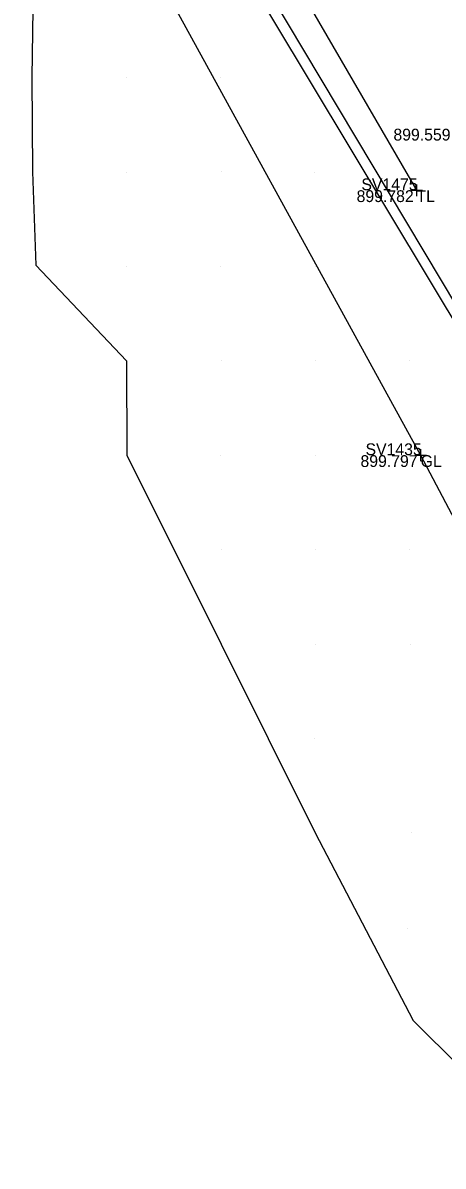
# Model space of a CAD drawing. Extents: x 1918148 to 1919797, y 624701 to 627089.
# Drawn here: x 1918830.7 to 1918866.3, y 625511 to 625607.8 of the extents above; entities that cross this region are included whole.
import ezdxf

# ---------------------------------------------------------------- set-up
doc = ezdxf.new("R2010")
doc.units = 0
for name, color, linetype in [('DT_X_Terrain_Boundary', 7, 'Continuous'), ('Ground Shots', 7, 'Continuous'), ('RD_X_Fence', 7, 'Continuous'), ('SV_X_Shot_Marker', 7, 'Continuous'), ('SV_X_Text_Comment', 7, 'Continuous'), ('SV_X_Text_Elevation', 7, 'Continuous'), ('SV_X_Text_Name', 7, 'Continuous'), ('UT_X_Gas', 7, 'Continuous'), ('UT_X_Overhead_Combined', 7, 'Continuous'), ('UT_X_Telecom', 7, 'Continuous')]:
    doc.layers.add(name, color=color, linetype=linetype)

msp = doc.modelspace()

# ---------------------------------------------------------------- linework, layer by layer
at = {"layer": 'DT_X_Terrain_Boundary'}
msp.add_lwpolyline([(1918796.762, 625701.528), (1918837.417, 625633.441), (1918839.502, 625611.203), (1918831.565, 625610.956), (1918831.449, 625603.209), (1918831.49, 625595.21), (1918831.786, 625587.295), (1918839.47, 625579.205), (1918839.493, 625571.214), (1918847.481, 625555.19), (1918855.45, 625539.209), (1918863.741, 625523.315), (1918871.72, 625515.381), (1918879.451, 625499.232)], dxfattribs=at)
at = {"layer": 'Ground Shots'}
for p, q in [((1918831.449, 625603.209), (1918831.449, 625603.209)), ((1918839.444, 625603.191), (1918839.444, 625603.191)), ((1918847.457, 625603.198), (1918847.457, 625603.198)), ((1918831.49, 625595.21), (1918831.49, 625595.21)), ((1918839.481, 625595.196), (1918839.481, 625595.196)), ((1918847.504, 625595.203), (1918847.504, 625595.203)), ((1918855.398, 625595.153), (1918855.398, 625595.153)), ((1918831.786, 625587.295), (1918831.786, 625587.295)), ((1918839.441, 625587.187), (1918839.441, 625587.187)), ((1918847.455, 625587.205), (1918847.455, 625587.205)), ((1918855.471, 625587.23), (1918855.471, 625587.23)), ((1918839.47, 625579.205), (1918839.47, 625579.205)), ((1918847.476, 625579.197), (1918847.476, 625579.197)), ((1918855.489, 625579.212), (1918855.489, 625579.212)), ((1918863.456, 625579.203), (1918863.456, 625579.203)), ((1918839.493, 625571.214), (1918839.493, 625571.214)), ((1918847.459, 625571.176), (1918847.459, 625571.176)), ((1918855.445, 625571.172), (1918855.445, 625571.172)), ((1918863.482, 625571.147), (1918863.482, 625571.147)), ((1918847.487, 625563.193), (1918847.487, 625563.193)), ((1918855.48, 625563.206), (1918855.48, 625563.206)), ((1918863.466, 625563.204), (1918863.466, 625563.204)), ((1918847.481, 625555.19), (1918847.481, 625555.19)), ((1918855.469, 625555.204), (1918855.469, 625555.204)), ((1918863.488, 625555.203), (1918863.488, 625555.203)), ((1918855.353, 625547.174), (1918855.353, 625547.174)), ((1918855.45, 625539.209), (1918855.45, 625539.209)), ((1918863.635, 625539.207), (1918863.635, 625539.207)), ((1918863.259, 625531.112), (1918863.259, 625531.112)), ((1918863.741, 625523.315), (1918863.741, 625523.315))]:
    msp.add_line(p, q, dxfattribs=at)
at = {"layer": 'RD_X_Fence'}
msp.add_lwpolyline([(1918745.788, 625786.434), (1918772.784, 625741.746), (1918796.762, 625701.528), (1918837.417, 625633.441), (1918845.82, 625619.995), (1919000.613, 625360.91)], dxfattribs=at)
at = {"layer": 'SV_X_Shot_Marker'}
for p, q in [((1918863.519, 625593.652), (1918864.519, 625593.652)), ((1918864.019, 625594.152), (1918864.019, 625593.152)), ((1918864.019, 625593.652), (1918864.019, 625593.652)), ((1918864.37, 625571.708), (1918864.37, 625570.708)), ((1918863.87, 625571.208), (1918864.87, 625571.208)), ((1918864.37, 625571.208), (1918864.37, 625571.208))]:
    msp.add_line(p, q, dxfattribs=at)
at = {"layer": 'UT_X_Gas'}
msp.add_lwpolyline([(1918759.168, 625917.084), (1918754.306, 625900.243), (1918749.452, 625846.761), (1918748.461, 625829.004), (1918743.942, 625797.46), (1918743.006, 625773.569), (1918765.829, 625740.859), (1918795.68, 625692.777), (1918822.428, 625647.505), (1918838.928, 625617.602), (1918864.37, 625571.208), (1918888.363, 625525.758), (1918914.136, 625478.379), (1918935.187, 625439.317), (1918956.473, 625399.657), (1918975.299, 625371.47), (1919011.933, 625334.484), (1919018.035, 625313.569)], dxfattribs=at)
at = {"layer": 'UT_X_Overhead_Combined'}
msp.add_lwpolyline([(1918749.028, 625800.122), (1918759.416, 625761.901), (1918898.018, 625531.272), (1919016.404, 625331.435)], dxfattribs=at)
at = {"layer": 'UT_X_Telecom'}
msp.add_lwpolyline([(1918746.049, 625787.637), (1918759.455, 625770.257), (1918759.455, 625770.257), (1918782.324, 625734.011), (1918799.096, 625706.156), (1918807.733, 625686.593), (1918828.088, 625655.331), (1918848.13, 625621.061), (1918864.019, 625593.652)], dxfattribs=at)

# ---------------------------------------------------------------- texts
at = {"layer": 'SV_X_Text_Comment'}
for s, p in [('TL', (1918864.019, 625592.652)), ('GL', (1918864.37, 625570.208))]:
    msp.add_text(s, height=1, dxfattribs=at).set_placement(p)
at = {"layer": 'SV_X_Text_Elevation'}
for s, p in [('899.559', (1918862.064, 625597.864)), ('899.782', (1918858.946, 625592.652)), ('899.797', (1918859.274, 625570.208))]:
    msp.add_text(s, height=1, dxfattribs=at).set_placement(p)
at = {"layer": 'SV_X_Text_Name'}
for s, p in [('SV1475', (1918859.35, 625593.652)), ('SV1435', (1918859.701, 625571.208))]:
    msp.add_text(s, height=1, dxfattribs=at).set_placement(p)

doc.saveas('drawing.dxf')
